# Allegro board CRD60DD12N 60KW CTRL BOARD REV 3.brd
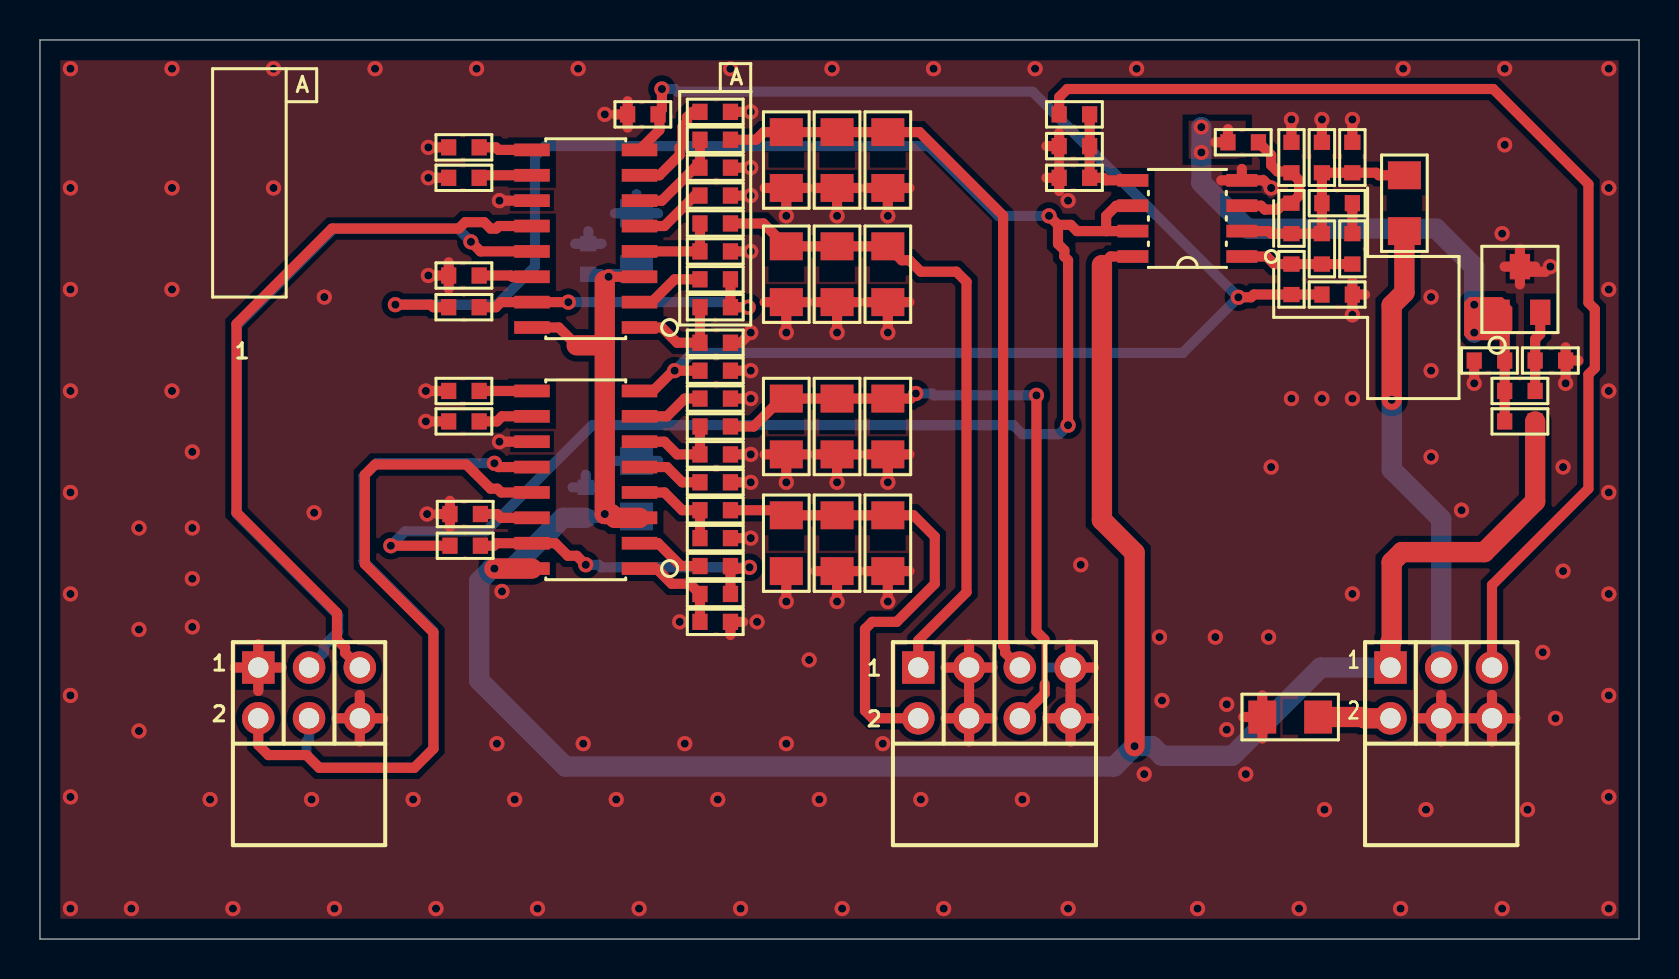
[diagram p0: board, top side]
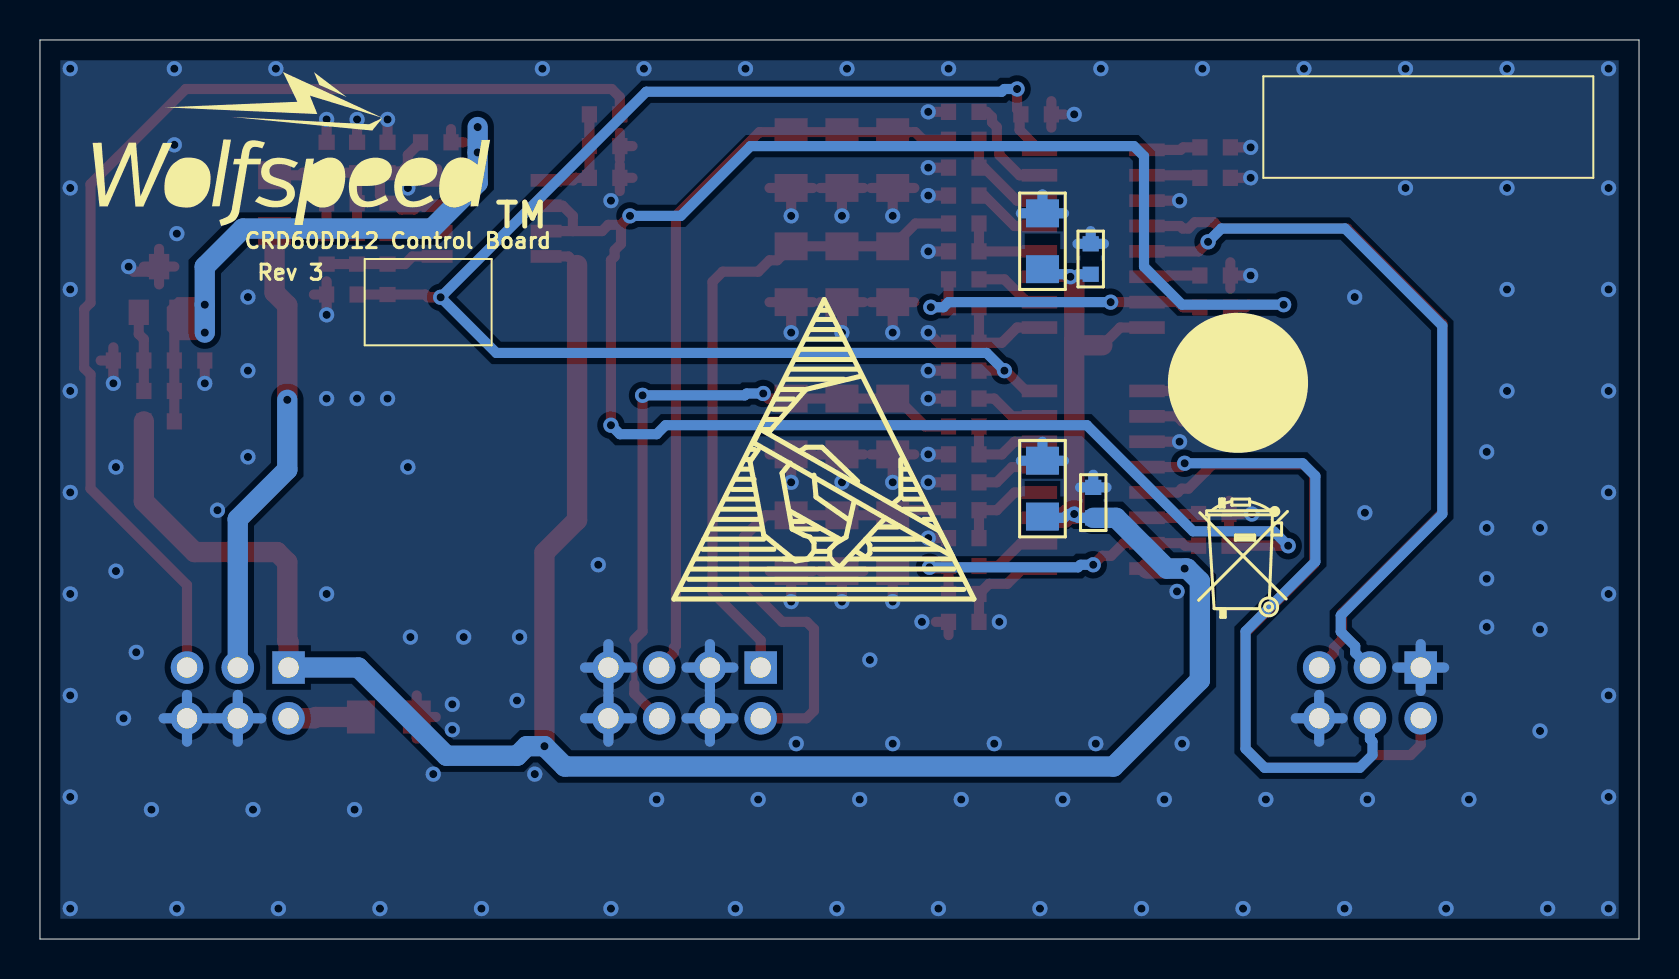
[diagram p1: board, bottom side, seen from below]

Outline 80 x 45 mm; copper layers: TOP, BOTTOM. Coordinates in mm from the lower left corner of the outline.
Outline path: 0,45 0,0 80,0 80,45 0,45

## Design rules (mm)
nets with their own width: min track width 0.305; nets PH2L_CS
nets with their own width: min track width 0.508; nets +12V_HV GND_SIGNAL N00590 N00889 N00944 N00959 N01249 N01910 N01917 N01924 N02476 N02561 N02568 N05010 N08645 N08649 N08677 N08793 N08893 N08901 N09025 N09069 N09077 N09269 N11985 N13290 N13315 N13401 N17251 PH1H_CS PH1L_CS PH2H_CS PV_-VE PWM1H PWM1L PWM2H PWM2L V_IN_SENSE V_OUT_SENSE VREF

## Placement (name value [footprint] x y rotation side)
C201  10uF  [1206]  29.84 34.92 90 bottom
C202  1uF  [0603]  21.21 33.21 180 top
C203  0.1uF  [0603]  33.78 41.4 0 top
C204  180pF  [0603]  30.16 41.27 180 top
C205  470pF  [0603]  33.78 34.42 0 top
C206  470pF  [0603]  33.78 38.61 0 top
C207  10nF  [0603]  64.14 34.54 90 top
C208  0.22uF  [0603]  65.66 34.54 90 top
C209  1nF  [0603]  62.61 36.07 90 top
C210  1nF  [0603]  62.61 39.12 90 top
C211  10uF  [1206]  29.84 22.54 90 bottom
C216  470pF  [0603]  33.78 24.26 0 top
C217  470pF  [0603]  33.78 20.07 0 top
C220  0.1uF  [0603]  33.78 27.05 0 top
C221  1uF  [0603]  21.27 21.27 180 top
C223  180pF  [0603]  33.78 28.45 0 top
C224  4.7uF  [0603]  72.52 28.96 180 top
C225  100nF  [0603]  27.43 34.04 90 bottom
C226  100nF  [0603]  27.3 21.84 90 bottom
C227  1nF  [0603]  51.75 38.1 180 top
CON217  HEADER 3X2  [CON_2MM54_3X2_RA]  67.56 13.59 180 top
CON218  HEADER 3X2  [CON_2MM54_3X2_RA]  10.92 13.59 180 top
CON219  HEADER 4X2  [CON_2MM54_4X2_RA]  43.94 13.59 180 top
NOREF  -  []  -97.79 -185.67 0 top
NOREF#2  -  []  -70.36 -43.94 0 top
NOREF#3  -  []  0 0 90 top
NOREF#4  -  []  0 0 0 top
NOREF#5  -  []  40.26 21.46 180 bottom
NOREF#6  -  []  17.27 19.18 180 bottom
NOREF#7  -  []  77.47 35.56 180 bottom
NOREF#8  -  []  19.56 28.07 180 bottom
R202  88.7K  [0603]  21.21 31.62 0 top
R204  174K  [0603]  33.78 33.02 0 top
R205  22.1K  [0603]  33.78 29.84 0 top
R206  27.4K  [0603]  33.78 31.62 0 top
R207  330k  [0603]  33.78 37.21 0 top
R208  73.2K  [0603]  21.21 38.1 180 top
R209  73.2K  [0603]  21.21 39.62 180 top
R210  4.7K  [0603]  33.78 35.81 180 top
R211  4.7K  [0603]  33.78 40.01 180 top
R212  18  [1206]  42.42 33.27 270 top
R213  18  [1206]  39.88 33.27 270 top
R214  18  [1206]  42.42 38.99 270 top
R215  18  [1206]  37.34 38.99 270 top
R216  1k  [0603]  64.9 32.26 0 top
R217  2k  [0603]  62.61 33.02 90 top
R218  0R  [0603]  60.2 39.88 0 top
R219  24.9K  [1206]  68.26 36.83 90 top
R220  100k  [0603]  64.9 36.83 180 top
R221  19.6K  [0603]  64.14 39.12 90 top
R222  DNP  [0603]  65.66 39.12 90 top
R223  18  [1206]  37.34 33.27 270 top
R224  18  [1206]  39.88 38.99 270 top
R235  18  [1206]  39.88 25.65 270 top
R236  18  [1206]  42.42 19.81 270 top
R237  27.4K  [0603]  33.78 17.27 0 top
R238  73.2K  [0603]  21.21 25.91 180 top
R241  330k  [0603]  33.78 22.86 0 top
R243  88.7K  [0603]  21.27 19.68 0 top
R244  174K  [0603]  33.78 18.67 0 top
R247  18  [1206]  39.88 19.81 270 top
R248  4.7K  [0603]  33.78 25.65 180 top
R250  18  [1206]  37.34 19.81 270 top
R251  18  [1206]  42.42 25.65 270 top
R252  0R  [0603]  74.04 27.43 0 top
R253  10k  [0603]  75.56 28.96 0 top
R254  73.2K  [0603]  21.21 27.43 180 top
R255  5.6k  [0603]  74.04 25.91 180 top
R256  18  [1206]  37.34 25.65 270 top
R260  22.1K  [0603]  33.78 15.88 0 top
R261  4.7K  [0603]  33.78 21.46 180 top
R262  0R  [1206]  62.55 11.11 180 top
R263  100k  [0603]  51.75 41.27 0 top
R264  56K  [0603]  51.75 39.69 180 top
U201  UCC28220D  [SOIC-16]  27.3 35.05 90 top
U202  LM358  [SOIC-8]  57.4 36.07 90 top
U203  UCC28220D  [SOIC-16]  27.3 22.99 90 top
U204  TL431  [SOT-23]  74.04 32.51 0 top

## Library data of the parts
C201-C211 C216 C217 C220 C221 C223-C227 = CAP NP
CON217 CON218 = HEADER 3X2
CON219 = HEADER 4X2
R202 R204-R224 R235-R238 R241 R243 R244 R247 R248 R250-R256 R260-R264 = RESISTOR
U201 U203 = UCC28220D
U202 = LM358
U204 = TL431_0

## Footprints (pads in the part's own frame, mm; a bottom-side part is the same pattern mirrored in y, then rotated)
0603
  rect 0.762x0.813 smd: 1(-0.762,0) 2(0.762,0)
1206
  rect 1.397x1.651 smd: 1(-1.397,0) 2(1.397,0)
CON_2MM54_3X2_RA
  rect 1.626x1.626 hole 1.016: 1(0,0)
  round 1.626 hole 1.016: 2(0,2.54) 3(-2.54,0) 4(-2.54,2.54) 5(-5.08,0) 6(-5.08,2.54)
CON_2MM54_4X2_RA
  rect 1.626x1.626 hole 1.016: 1(0,0)
  round 1.626 hole 1.016: 2(0,2.54) 3(-2.54,0) 4(-2.54,2.54) 5(-5.08,0) 6(-5.08,2.54) 7(-7.62,0) 8(-7.62,2.54)
SOIC-8
  rect 0.635x1.549 smd: 1(-1.905,-2.725) 2(-0.635,-2.725) 3(0.635,-2.725) 4(1.905,-2.725) 5(1.905,2.725) 6(0.635,2.725) 7(-0.635,2.725) 8(-1.905,2.725)
SOIC-16
  rect 0.635x1.778 smd: 1(-4.445,-2.69) 2(-3.175,-2.69) 3(-1.905,-2.69) 4(-0.635,-2.69) 5(0.635,-2.69) 6(1.905,-2.69) 7(3.175,-2.69) 8(4.445,-2.69) 9(4.445,2.69) 10(3.175,2.69) 11(1.905,2.69) 12(0.635,2.69) 13(-0.635,2.69) 14(-1.905,2.69) 15(-3.175,2.69) 16(-4.445,2.69)
SOT-23
  rect 1.016x1.27 smd: 1(-1.016,-1.143) 2(1.016,-1.143) 3(0,1.143)

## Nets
+12V_HV: C201.1 C211.1 C225.1 C226.1 CON217.1 R255.1 U201.3(VDD) U201.16(VIN) U202.8(VCC) U203.3(VDD) U203.16(VIN)
GND_SIGNAL: C201.2 C202.2 C203.2 C204.2 C205.2 C206.2 C210.2 C211.2 C216.2 C217.2 C220.2 C221.2 C223.2 C224.2 C225.2 C226.2 C227.2 CON217.4 CON217.6 CON218.1 CON218.6 CON219.3 CON219.4 CON219.7 CON219.8 R205.2 R207.2 R208.2 R209.2 R212.2 R213.2 R214.2 R215.2 R216.2 R221.2 R222.2 R223.2 R224.2 R235.2 R236.2 R238.2 R241.2 R247.2 R250.2 R251.2 R253.2 R254.2 R256.2 R260.2 R262.2 R264.2 U201.11(GND) U202.4(GND) U203.11(GND) U204.3(A)
PH1H_CS: CON219.1 R210.1 R212.1 R213.1 R223.1
PH1L_CS: CON219.5 R211.1 R214.1 R215.1 R224.1
PH2H_CS: CON219.2 R236.1 R247.1 R250.1 R261.1
PH2L_CS: CON219.6 R235.1 R248.1 R251.1 R256.1
PV_-VE: CON217.2 R262.1
PWM1H: CON218.3 U201.13(OUT1)
PWM1L: CON218.5 U201.12(OUT2)
PWM2H: CON218.2 U203.13(OUT1)
PWM2L: CON218.4 U203.12(OUT2)
V_IN_SENSE: CON217.5 R263.1
V_OUT_SENSE: CON217.3 R219.1
VREF: C224.1 R218.1 R252.1 R255.2 U204.1(K)
N00590: R204.1 U201.2(LINEHYS)
N00889: R205.1 R206.1 U201.1(LINEOV)
N00944: R202.1 R243.1 U202.6(-IN) U202.7(OUT)
N00959: R202.2 R204.2 R206.2 U201.15(LINEUV)
N01249: C205.1 R210.2 U201.4(CS1)
N01910: C204.1 C223.1 R216.1 R217.1 U201.8(CTRL) U203.8(CTRL)
N01917: C203.1 U201.7(SS)
N01924: R207.1 U201.5(SLOPE)
N02476: C206.1 R211.2 U201.6(CS2)
N02561: R209.1 U201.9(DISCHG)
N02568: R208.1 U201.10(CHG)
N05010: C202.1 U201.14(REF)
N08645: R244.1 U203.2(LINEHYS)
N08649: R237.1 R260.1 U203.1(LINEOV)
N08677: R237.2 R243.2 R244.2 U203.15(LINEUV)
N08793: C217.1 R261.2 U203.4(CS1)
N08893: C220.1 U203.7(SS)
N08901: R241.1 U203.5(SLOPE)
N09025: C216.1 R248.2 U203.6(CS2)
N09069: R254.1 U203.9(DISCHG)
N09077: R238.1 U203.10(CHG)
N09269: C221.1 U203.14(REF)
N11985: C207.1 C208.1 R217.2 U202.1(OUT)
N13290: C209.2 C210.1 R218.2 U202.3(+IN)
N13315: C207.2 C209.1 R219.2 R220.2 R221.1 R222.1 U202.2(-IN)
N13401: C208.2 R220.1
N17251: R252.2 R253.1 U204.2(REF)
N12007592: C227.1 R263.2 R264.1 U202.5(+IN)

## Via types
v1: diameter 0.762, hole 0.406, TOP to BOTTOM, 166 vias

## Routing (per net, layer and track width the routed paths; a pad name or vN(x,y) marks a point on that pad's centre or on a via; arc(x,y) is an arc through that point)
+12V_HV: length 132.2
  TOP w0.508: 28.26,32.96 v1(28.45,33.15) U201.3 ; U202.8 53.56,34.16 53.13,33.73 ; 26.85,29.72 25.96,30.61 U201.16
  TOP w1.016: R255.1 74.8,21.91 72.26,19.37 68.14,19.37 67.63,18.86 67.63,14.92 67.56,14.86 CON217.1 ; 28.13,29.84 28,29.72 26.85,29.72 ; 28.13,29.84 28.26,29.72 v1(28.26,21.27) 28.57,21.27 28.77,21.08 U203.3 ; 28.13,29.84 28.26,29.97 28.26,32.96 ; U203.16 v1(22.73,18.54) ; 53.13,33.73 53.13,20.97 54.76,19.34 v1(54.76,9.65)
  BOTTOM w0.508: C226.1 28.07,21.08 v1(28.26,21.27) 28.57,21.27 28.77,21.08 29.34,21.08 29.4,21.15 C211.1 ; C225.1 28.07,33.27 28.19,33.15 v1(28.45,33.15) 28.57,33.27 29.34,33.27 29.59,33.53 C201.1
  BOTTOM w1.016: CON217.1 64.07,13.59 59.66,9.18 56.13,9.18 55.65,9.65 v1(54.76,9.65) 53.75,8.64 26.29,8.64 21.97,12.95 21.97,17.91 22.61,18.54 v1(22.73,18.54) 23.62,18.54 26.16,21.08 C226.1
GND_SIGNAL: length 175.3
  TOP w0.508: R214.2 v1(42.42,36.2) ; R214.2 43.5,37.59 ; R214.2 41.34,37.59 ; 73.28,33.66 U204.3 ; U204.3 74.8,33.66 ; U204.3 74.55,33.4 75.31,33.4 v1(75.56,33.66) ; U204.3 74.04,34.54 ; U204.3 74.04,32.77 ; R236.2 43.5,18.41 ; R236.2 v1(42.42,16.89) ; R236.2 41.34,18.41 ; C203.2 v1(35.56,41.4) ; C210.2 v1(62.61,41.02) ; 20.45,32.55 C202.2 ; C202.2 v1(19.43,33.21) ; C202.2 20.45,33.87 ; U202.4 60.13,38.55 ; U202.4 59.1,37.97 ; U202.4 61.21,37.97 v1(61.59,37.59) ; C206.2 v1(35.56,38.61) ; R221.2 v1(64.14,41.02) ; C223.2 v1(35.56,28.45) ; CON219.7 51.56,14.76 ; CON219.7 51.56,12.42 ; CON219.7 52.73,13.59 ; 50.35,39.69 R264.2 ; R264.2 50.99,39.03 ; R264.2 50.99,40.35 ; 61.15,10.03 R262.2 ; R262.2 61.15,12.19 ; R262.2 60.2,11.11 ; 9.75,13.59 CON218.1 ; CON218.1 10.92,14.76 ; CON218.1 12.09,13.59 ; CON218.1 10.92,12.42 ; R235.2 v1(39.88,22.86) ; R235.2 40.96,24.26 ; R235.2 38.8,24.26 ; R253.2 v1(76.33,27.81) ; R253.2 76.96,28.96 ; R253.2 76.33,29.62 ; U203.11 v1(22.99,24.89) ; CON219.3 46.48,14.76 ; CON219.3 46.48,12.42 ; CON219.3 45.31,13.59 ; CON219.3 47.65,13.59 ; 29.4,40.61 C204.2 ; C204.2 28.76,41.27 ; C204.2 29.4,41.94 ; 38.8,18.41 R247.2 ; R247.2 40.96,18.41 ; R247.2 v1(39.88,16.89) ; 50.39,11.05 CON219.8 ; CON219.8 51.56,9.88 ; CON219.8 52.73,11.05 ; CON219.8 51.56,12.22 ; 45.31,11.05 CON219.4 ; CON219.4 46.48,12.22 ; CON219.4 47.65,11.05 ; CON219.4 46.48,9.88 ; R224.2 v1(39.88,36.2) ; R224.2 40.96,37.59 ; R224.2 38.8,37.59 ; R209.2 v1(19.43,39.62) ; R208.2 v1(19.43,38.1) ; 41.34,31.88 42.42,31.88 ; 42.42,31.88 v1(42.42,30.35) ; 42.42,31.88 43.5,31.88 ; 37.34,31.88 v1(37.34,30.35) ; 37.34,31.88 36.26,31.88 ; 37.34,31.88 38.42,31.88 ; 38.8,31.88 39.88,31.88 ; 39.88,31.88 v1(39.88,30.35) ; 39.88,31.88 40.96,31.88 ; v1(71.12,21.46) 71.12,21.59 ; R216.2 66.29,32.26 ; R216.2 65.66,32.92 ; R216.2 v1(65.66,31.24) ; 36.26,24.26 R256.2 ; R256.2 v1(37.34,22.86) ; R256.2 38.42,24.26 ; R222.2 v1(65.66,41.02) ; C224.2 v1(71.75,27.81) ; CON217.4 70.1,12.22 ; CON217.4 70.1,9.88 ; CON217.4 71.27,11.05 ; CON217.4 68.94,11.05 ; CON218.6 16,12.22 ; CON218.6 16,9.88 ; CON218.6 14.83,11.05 ; CON218.6 17.17,11.05 ; C227.2 50.99,38.76 ; C227.2 50.99,37.44 ; C227.2 50.35,38.1 ; R238.2 v1(19.3,25.91) ; C216.2 v1(35.56,24.26) ; R251.2 v1(42.42,22.86) ; R251.2 43.5,24.26 ; R251.2 41.34,24.26 ; C221.2 20.51,21.93 ; C221.2 19.87,21.27 ; C221.2 20.51,20.61 ; 72.64,9.88 CON217.6 ; CON217.6 73.81,11.05 ; CON217.6 71.48,11.05 ; CON217.6 72.64,12.22 ; R215.2 38.42,37.59 ; R215.2 36.26,37.59 ; R215.2 v1(37.34,36.2) ; R241.2 v1(35.56,22.86) ; C205.2 v1(35.56,34.42) ; U201.11 v1(22.99,36.96) ; R250.2 v1(37.34,16.89) ; C217.2 v1(35.56,20.07) ; C220.2 v1(35.56,27.05) ; R207.2 v1(35.56,37.21) ; R205.2 35.05,29.84 v1(35.56,30.35) ; R254.2 v1(19.3,27.43) ; 34.54,15.21 R260.2 35.18,15.88
  BOTTOM w0.508: CON217.6 72.64,12.22 ; CON217.6 71.48,11.05 ; CON217.6 73.81,11.05 ; CON217.6 72.64,9.88 ; C226.2 27.97,22.61 ; C226.2 26.64,22.61 ; C226.2 27.3,23.24 ; C201.2 29.84,37.28 ; C201.2 28.76,36.32 ; C201.2 30.93,36.32 ; C225.2 27.43,35.43 ; C225.2 28.09,34.8 ; C225.2 26.77,34.8 ; 46.48,9.88 CON219.4 ; CON219.4 46.48,12.22 ; CON219.4 47.65,11.05 ; CON219.4 45.31,11.05 ; CON219.7 51.56,14.76 ; CON219.7 50.39,13.59 ; CON219.7 51.56,12.42 ; CON219.7 52.73,13.59 ; CON219.8 51.56,12.22 ; CON219.8 50.39,11.05 ; CON219.8 52.73,11.05 ; CON219.8 51.56,9.88 ; 28.76,23.94 C211.2 ; C211.2 29.84,24.89 ; C211.2 30.93,23.94 ; CON218.6 17.17,11.05 ; CON218.6 16,12.22 ; CON218.6 16,9.88 ; CON218.6 14.83,11.05 ; CON218.1 12.09,13.59 ; CON218.1 9.75,13.59 ; CON218.1 10.92,14.76 ; CON218.1 10.92,12.42 ; CON219.3 46.48,14.76 ; CON219.3 46.48,12.42 ; CON219.3 45.31,13.59 ; CON219.3 47.65,13.59 ; 70.1,9.88 CON217.4 ; CON217.4 71.27,11.05 ; CON217.4 68.94,11.05 ; CON217.4 70.1,12.22
  vias: v1(1.52,43.56) v1(1.52,37.59) v1(1.52,32.51) v1(1.52,27.43) v1(1.52,22.35) v1(1.52,17.27) v1(1.52,12.19) v1(1.52,7.11) v1(1.52,1.52) v1(4.57,1.52) v1(4.95,20.57) v1(4.95,15.49) v1(4.95,10.41) v1(6.6,43.56) v1(6.6,37.59) v1(6.6,32.51) v1(6.6,27.43) v1(7.62,24.38) v1(7.62,20.57) v1(7.62,18.03) v1(7.62,15.62) v1(8.51,6.99) v1(9.65,1.52) v1(11.68,43.56) v1(11.68,37.59) v1(13.59,6.99) v1(13.72,21.34) v1(14.22,32.13) v1(14.73,1.52) v1(16.76,43.56) v1(18.67,6.99) v1(19.37,21.27) v1(19.81,1.52) v1(21.84,43.56) v1(22.86,9.78) v1(23.11,17.4) v1(23.75,6.99) v1(24.89,1.52) v1(26.92,43.56) v1(27.18,9.78) v1(28.26,41.27) v1(28.83,6.99) v1(29.97,1.52) v1(32,15.88) v1(32.26,9.78) v1(33.91,6.99) v1(34.54,43.56) v1(35.05,1.52) v1(35.88,15.88) v1(37.34,9.78) v1(38.48,13.97) v1(38.99,6.99) v1(39.62,43.56) v1(40.13,1.52) v1(42.16,9.78) v1(44.07,6.99) v1(44.7,43.56) v1(45.21,1.52) v1(49.15,6.99) v1(49.78,43.56) v1(51.44,36.96) v1(51.44,1.52) v1(52.07,18.73) v1(54.86,43.56) v1(55.24,8.26) v1(56.01,15.11) v1(56.13,11.94) v1(57.91,1.52) v1(58.8,15.11) v1(59.37,11.75) v1(59.37,10.48) v1(60.33,8.26) v1(61.47,15.11) v1(61.59,23.62) v1(62.61,27.05) v1(62.99,1.52) v1(64.14,27.05) v1(64.26,6.48) v1(65.66,27.05) v1(65.66,17.27) v1(68.07,1.52) v1(68.2,43.56) v1(69.34,6.48) v1(69.6,32.13) v1(69.6,28.45) v1(69.6,24.13) v1(73.15,35.31) v1(73.15,1.52) v1(73.28,43.56) v1(73.28,39.75) v1(74.42,6.48) v1(75.18,14.35) v1(75.82,11.05) v1(76.2,23.62) v1(76.2,18.41) v1(78.49,43.56) v1(78.49,37.59) v1(78.49,32.51) v1(78.49,27.43) v1(78.49,22.35) v1(78.49,17.27) v1(78.49,12.19) v1(78.49,7.11) v1(78.49,1.52)
PH1H_CS: length 33.3
  TOP w0.508: R210.1 36.2,35.81 R223.1 R213.1 R212.1 43.12,33.97 43.5,33.97 44.07,33.4 45.85,33.4 46.35,32.89 46.35,17.36 43.94,14.95 CON219.1
PH1L_CS: length 38.5
  TOP w0.508: R211.1 35.83,40.01 36.21,40.39 R215.1 R224.1 R214.1 44.01,40.39 48.18,36.21 48.18,14.68 48.29,14.58 48.29,14.33 CON219.5
PH2H_CS: length 24.5
  TOP w0.508: CON219.2 41.66,11.05 41.27,11.43 41.27,15.51 41.64,15.88 42.86,15.88 44.77,17.78 44.77,20.14 43.7,21.21 R236.1 R247.1 R250.1 37.08,21.46 R261.1
PH2L_CS: length 32.9
  TOP w0.305: 50.27,14.98 50.27,12.76
  TOP w0.508: 50.27,12.76 50.27,12.29 CON219.6 ; 50.27,14.98 49.85,15.4 v1(49.85,27.21) ; R248.1 35.71,25.65 37.11,27.05 R256.1 R235.1 R251.1 43.56,27.05 v1(43.81,27.3)
  BOTTOM w0.508: v1(49.85,27.21) 44.74,27.21 44.65,27.3 v1(43.81,27.3)
PV_-VE: length 3.6
  TOP w1.016: R262.1 66.21,11.11 66.27,11.05 CON217.2
PWM1H: length 37.1
  TOP w0.508: U201.13 22.04,34.42 v1(21.56,34.9)
  BOTTOM w0.508: CON218.3 14.2,14.33 14.2,14.66 14.92,15.38 14.92,16.19 9.84,21.27 9.84,30.7 14.7,35.56 20.9,35.56 v1(21.56,34.9)
PWM1L: length 36.8
  TOP w0.508: U201.12 22.95,35.69 22.82,35.56 22.54,35.56 22.23,35.88 21.27,35.88 20.95,35.56 14.6,35.56 9.83,30.79 9.83,21.35 14.86,16.32 14.86,14.99 15.27,14.58 15.27,14.33 CON218.5 16,13.59
PWM2H: length 35.2
  TOP w0.508: U203.13 23.07,22.35 22.88,22.54 22.54,22.54 21.7,23.38 21.7,23.38 21.34,23.75 16.76,23.75 16.26,23.24 16.26,18.76 19.68,15.34 19.68,9.53 18.73,8.57 13.97,8.57 13.34,9.21 11.43,9.21 10.92,9.72 CON218.2
PWM2L: length 32.8
  TOP w0.508: U203.12 22.92,23.62 v1(22.73,23.81)
  BOTTOM w0.508: CON218.4 13.46,10.01 13.34,9.88 13.34,9.21 13.97,8.57 18.73,8.57 19.68,9.53 19.68,15.4 16.19,18.89 16.19,23.18 16.83,23.81 v1(22.73,23.81)
V_IN_SENSE: length 55.9
  TOP w0.508: CON217.5 72.64,17.72 77.47,22.54 77.47,28.26 77.79,28.57 77.79,31.53 77.47,31.85 77.47,37.78 72.71,42.55 51.4,42.55 50.99,42.14 R263.1
V_OUT_SENSE: length 23.1
  TOP w1.016: R219.1 68.26,32.36 67.63,31.72 v1(67.63,26.99)
  BOTTOM w1.016: v1(67.63,26.99) 67.63,23.5 70.1,21.02 CON217.3
VREF: length 28.3
  TOP w0.508: R255.2 R252.1 C224.1 73.28,31.11 U204.1 ; 59.44,40.54 R218.1 58.8,39.88
  BOTTOM w1.016: v1(58.1,40.64) v1(58.1,39.37) 58.1,37.85 60.39,35.56 69.85,35.56 71.75,33.66 v1(71.75,31.75) v1(71.75,30.35)
N00590: length 3.5
  TOP w0.508: U201.2 30.61,31.88 31.75,33.02 R204.1
N00889: length 5.1
  TOP w0.508: R206.1 R205.1 31.88,29.84 31.11,30.61 U201.1 29.97,30.61
N00944: length 100.2
  TOP w0.508: R243.1 v1(17.55,19.68) ; 50.93,35.75 v1(50.48,36.2) ; 50.93,35.75 51.57,35.75 51.88,35.43 53.34,35.43 ; 50.93,35.75 50.93,34.79 51.25,34.48 51.25,34.16 51.44,33.97 v1(51.44,25.72) ; 53.34,35.43 U202.7 ; 53.34,35.43 53.34,36.2 53.85,36.7 54.68,36.7 ; R202.1 19.68,31.62 19.56,31.75 v1(17.78,31.75)
  BOTTOM w0.508: v1(50.48,36.2) 47.94,36.2 44.45,39.69 25.27,39.69 24.77,39.18 24.77,33.66 22.86,31.75 v1(17.78,31.75) ; v1(51.44,25.72) 50.99,25.27 49.15,25.27 48.7,25.72 27.62,25.72 22.31,20.41 18.27,20.41 v1(17.55,19.68)
N00959: length 16
  TOP w0.508: R202.2 22.81,31.62 23.06,31.88 U201.15 v1(26.43,31.88) ; R204.2 R206.2 v1(35.43,31.62)
  BOTTOM w0.508: v1(26.43,31.88) 34.54,31.88 34.8,31.62 v1(35.43,31.62)
N01249: length 4.4
  TOP w0.508: U201.4 C205.1 R210.2
N01910: length 74.1
  TOP w0.508: U201.8 30.99,40.49 30.99,41.21 C204.1 30.92,41.34 31.11,41.53 v1(31.11,42.55) ; U203.8 30.67,27.43 31.69,28.45 v1(31.75,28.45) C223.1 ; R216.1 R217.1 60.73,32.26 60.59,32.12 v1(59.95,32.12)
  BOTTOM w0.508: v1(31.11,42.55) 31.75,42.55 31.89,42.41 49.67,42.41 v1(59.95,32.12) 57.17,29.34 32.64,29.34 v1(31.75,28.45)
N01917: length 5.2
  TOP w0.508: C203.1 32.64,41.4 32.37,41.13 32.37,40.88 32.13,40.64 32.13,39.75 32,39.62 32,39.24 30.99,38.23 U201.7
N01924: length 3.7
  TOP w0.508: 29.97,35.69 U201.5 31.24,35.69 32.77,37.21 R207.1
N02476: length 5.1
  TOP w0.508: U201.6 31.11,36.96 32.77,38.61 C206.1 R211.2
N02561: length 2.7
  TOP w0.508: R209.1 22.81,39.62 22.94,39.5 U201.9 24.64,39.5
N02568: length 2.7
  TOP w0.508: R208.1 22.1,38.23 U201.10
N05010: length 2.7
  TOP w0.508: C202.1 23.56,33.21 23.62,33.15 U201.14
N08645: length 3.5
  TOP w0.508: U203.2 30.92,19.81 32.07,18.67 R244.1
N08649: length 5
  TOP w0.508: 29.97,18.54 U203.1 30.84,18.54 31.6,17.78 32.51,17.78 R237.1 R260.1
N08677: length 16.4
  TOP w0.508: v1(27.3,18.73) 26.86,19.18 26.41,19.18 25.78,19.81 U203.15 22.83,19.81 22.71,19.68 R243.2 ; R237.2 R244.2 34.67,18.54 35.43,18.54 v1(35.5,18.61)
  BOTTOM w0.508: v1(27.3,18.73) 27.94,18.73 28.07,18.61 v1(35.5,18.61)
N08793: length 4.8
  TOP w0.508: C217.1 R261.2 32.13,21.46 31.24,22.35 U203.4 29.97,22.35
N08893: length 3.4
  TOP w0.508: C220.1 32.26,27.05 31.37,26.16 U203.7
N08901: length 3.4
  TOP w0.508: R241.1 32.13,22.86 31.37,23.62 U203.5 29.97,23.62
N09025: length 4.7
  TOP w0.508: R248.2 C216.1 31.88,24.26 31.24,24.89 U203.6
N09069: length 2.6
  TOP w0.508: U203.9 R254.1
N09077: length 2.8
  TOP w0.508: 24.64,26.16 U203.10 23.11,26.16 22.86,25.91 R238.1
N09269: length 2.7
  TOP w0.508: C221.1 22.87,21.27 23.06,21.08 U203.14
N11985: length 5.7
  TOP w0.508: U202.1 61.37,34.16 61.75,33.78 R217.2 C207.1 C208.1
N13290: length 7.1
  TOP w0.508: R218.2 61.59,39.24 61.59,38.73 61.91,38.42 62.55,38.42 C210.1 62.99,37.97 62.99,37.21 C209.2 62.23,36.83 61.91,36.51 61.28,36.51 61.09,36.7 60.13,36.7
N13315: length 11.3
  TOP w0.508: R219.2 66.98,38.23 66.85,38.35 R222.1 R221.1 R220.2 C207.2 C209.1 61.59,35.31 61.47,35.43 U202.2
N13401: length 1.5
  TOP w0.508: R220.1 C208.2
N17251: length 4
  TOP w0.508: R252.2 R253.1 74.8,30.02 75.06,30.28 U204.2
N12007592: length 5.4
  TOP w0.508: U202.5 53.33,37.97 53.2,38.1 C227.1 R264.1 R263.2

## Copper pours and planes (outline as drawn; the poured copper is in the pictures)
GND_SIGNAL on TOP, BOTTOM: 1.02,1.02 1.02,43.98 78.98,43.98 78.98,1.02
VREF on TOP (solid shape): 73.66,31.62 73.66,30.48 73.15,29.97 71.5,29.97 71.25,30.23 71.25,31.88 71.5,32.13 73.15,32.13
VREF on TOP: 57.47,40.96 60.33,40.96 60.33,39.05 57.47,39.05

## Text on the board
Ref Des/Silkscreen Bottom: Rev 3 | CRD60DD12 Control Board
Ref Des/Silkscreen Top: 1 | A
DIMENSION: FIGURE | SIZE | 16.0 | 40.0 | DRILL CHART: TOP to BOTTOM | ALL UNITS ARE IN MILS | PLATED | QTY | 166 | 20
